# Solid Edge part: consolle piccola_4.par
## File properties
Last saved by: i.fialdini
Revision: 62
Tipo di contenuto documento: 0
Accuracy: 0.990
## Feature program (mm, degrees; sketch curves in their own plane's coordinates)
body "unnamed Body 1"
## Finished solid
Body 1: solid body, 40 faces, 94 edges, 62 vertices, 1 internal void.
  Faces by surface: spline 18, cylinder 14, plane 8
  Edges by curve: curve on surface 72, circle 8, ellipse 8, line 4, spline 2
Bounding box of the edges (mm; curved faces can reach further): 64.552 x 416.669 x 749.548, from (176.2822, -924.4912, -47.5677) to (240.8344, -507.8225, 701.9805).
Cylindrical faces by radius (mm): R4.75 x2, R6.25 x2, R6.5 x1, R8 x1, R9 x2, R10.5 x6
Planar faces by outward normal: +z 2, -x 2, -z 2, oblique 2
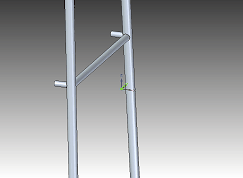
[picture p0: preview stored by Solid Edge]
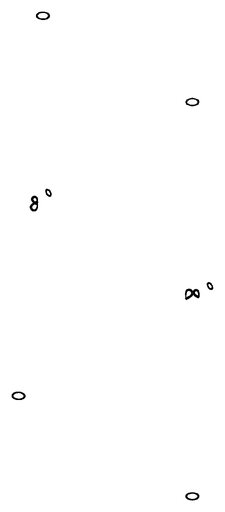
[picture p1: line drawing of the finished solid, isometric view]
